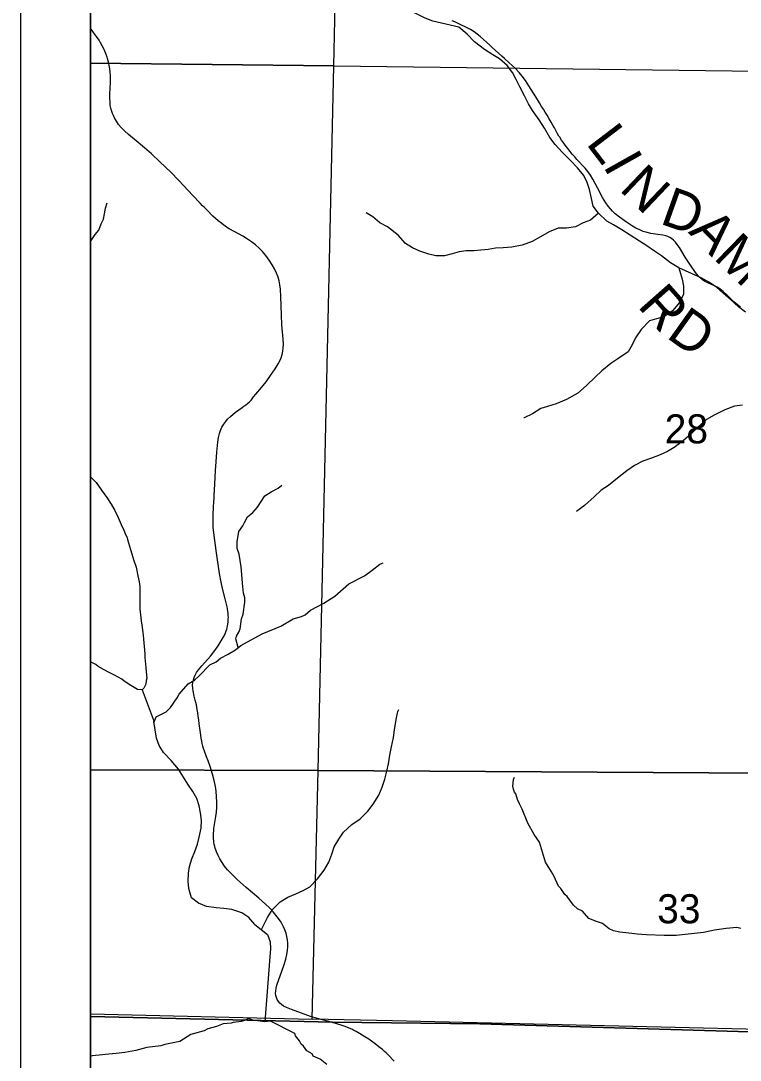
# Model space of a CAD drawing. Extents: x 0 to 34, y -8.9 to 22.
# Drawn here: x 23.617 to 24.652, y 15.928 to 17.424 of the extents above; entities that cross this region are included whole.
import ezdxf

# ---------------------------------------------------------------- set-up
doc = ezdxf.new("R2010")
doc.units = 0
for name, color, linetype in [('GM_X_Corporation', 7, 'Continuous'), ('GM_X_Minor_River', 7, 'Continuous'), ('GM_X_Section_Text', 7, 'Continuous'), ('GM_X_Township_Road', 7, 'Continuous'), ('GM_X_Township_Road_Text', 7, 'Continuous'), ('SH_Data', 7, 'Continuous')]:
    doc.layers.add(name, color=color, linetype=linetype)

msp = doc.modelspace()

# ---------------------------------------------------------------- linework, layer by layer
at = {"layer": 'GM_X_Corporation'}
msp.add_lwpolyline([(23.7167, 19.34), (23.7167, 14.6), (30.5167, 14.6)], dxfattribs=at)
for points in [[(23.7167, 19.34), (23.7167, 15.9913), (24.0651, 15.9828), (24.2771, 15.9807), (24.8268, 15.964), (25.6785, 15.9418), (25.7922, 15.939), (26.1186, 15.9366), (26.135, 17.3055), (26.1361, 17.3278), (26.1391, 17.8847), (26.1399, 18.3037), (25.7381, 18.312), (25.2083, 18.3108), (25.1045, 18.3117), (25.1124, 18.5932), (25.1216, 18.6194), (25.125, 18.6354), (25.1229, 18.6966), (25.1136, 18.8385), (25.1068, 18.8675), (25.1066, 19.3232), (25.0504, 19.3237), (24.5181, 19.3295)], [(23.7167, 18.338), (23.7167, 17.3635), (24.0671, 17.3595), (24.0882, 18.3313)], [(23.7167, 17.3635), (23.7167, 16.3462), (24.0445, 16.3452), (24.0671, 17.3595)], [(24.0671, 17.3595), (25.0983, 17.3466), (25.0882, 16.3389), (24.0445, 16.3452)], [(23.7167, 15.9913), (23.7167, 14.6), (28.1739, 14.6), (28.1809, 15.2987), (28.1918, 16.1509), (28.1846, 16.3341), (28.1817, 16.6637), (28.1928, 16.8054), (28.1882, 17.3108), (27.911, 17.3104), (27.4798, 17.3159), (27.0561, 17.3117), (26.7292, 17.3169), (26.394, 17.3229), (26.1361, 17.3278), (26.135, 17.3055), (26.1186, 15.9366), (25.7922, 15.939), (25.6785, 15.9418), (24.8268, 15.964), (24.2771, 15.9807), (24.0651, 15.9828)], [(23.7167, 16.3462), (23.7167, 15.9948), (24.0358, 15.9873), (24.0445, 16.3452)], [(24.0445, 16.3452), (25.0882, 16.3389), (25.0869, 15.9626), (24.1515, 15.9848), (24.0358, 15.9873)]]:
    msp.add_lwpolyline(points, close=True, dxfattribs=at)
at = {"layer": 'GM_X_Minor_River'}
for points in [[(24.2093, 17.4238), (24.1984, 17.428), (24.188, 17.4333), (24.1767, 17.4386), (24.167, 17.4439), (24.1569, 17.4461), (24.1447, 17.4466), (24.1333, 17.4447), (24.1214, 17.4428), (24.1107, 17.4417), (24.0993, 17.4394), (24.0897, 17.4386), (24.0787, 17.4394), (24.0679, 17.4436), (24.0577, 17.4478), (24.046, 17.4493), (24.0354, 17.4493), (24.0244, 17.4516), (24.0128, 17.455), (23.9838, 17.4816)], [(24.659, 17.0047), (24.649, 17.0127), (24.6372, 17.0238), (24.6276, 17.0317), (24.6173, 17.0408), (24.6065, 17.048), (24.5953, 17.0545), (24.5729, 17.0644), (24.5632, 17.0689), (24.5513, 17.0758), (24.5383, 17.0861), (24.5283, 17.0926), (24.5175, 17.1002), (24.5067, 17.107), (24.4934, 17.1158), (24.4815, 17.1235), (24.4692, 17.1308), (24.4595, 17.136), (24.4477, 17.1475), (24.4401, 17.1576), (24.4375, 17.1687), (24.4349, 17.1814), (24.4314, 17.1917), (24.4265, 17.2014), (24.4177, 17.2127), (24.4075, 17.223), (24.3957, 17.2352), (24.3855, 17.2462), (24.3778, 17.2563), (24.37, 17.2699), (24.3624, 17.2816), (24.353, 17.2952), (24.3472, 17.3049), (24.3412, 17.3161), (24.3348, 17.3293), (24.3291, 17.3397), (24.3241, 17.3498), (24.3165, 17.3599), (24.3054, 17.3695), (24.2958, 17.3755), (24.2838, 17.3828), (24.2694, 17.3939), (24.2588, 17.4053), (24.2466, 17.4152), (24.2093, 17.4238)], [(23.7167, 17.1072), (23.7177, 17.1081), (23.7236, 17.1166), (23.7288, 17.1228), (23.7321, 17.1319), (23.7354, 17.1388), (23.7371, 17.1464), (23.7385, 17.1548), (23.7407, 17.1625)], [(24.4477, 17.1475), (24.4364, 17.1372), (24.4256, 17.1334), (24.4148, 17.1277), (24.4018, 17.1259), (24.3896, 17.126), (24.3769, 17.1207), (24.3641, 17.1132), (24.3525, 17.1068), (24.3378, 17.1012), (24.3233, 17.0987), (24.3107, 17.0976), (24.2997, 17.0969), (24.289, 17.0953), (24.2787, 17.0942), (24.2684, 17.0934), (24.2574, 17.0934), (24.2474, 17.0919), (24.2371, 17.0888), (24.2263, 17.0862), (24.2138, 17.0858), (24.2036, 17.0885), (24.1909, 17.0927), (24.18, 17.0977), (24.1703, 17.1037), (24.1594, 17.1155), (24.1442, 17.1278), (24.133, 17.1335), (24.123, 17.1419), (24.1134, 17.1479)], [(24.5632, 17.0689), (24.5679, 17.0524), (24.5702, 17.0421), (24.5702, 17.0307), (24.5645, 17.0187), (24.5542, 17.0069), (24.5417, 16.9983), (24.531, 16.9952), (24.521, 16.9925), (24.5091, 16.98), (24.5011, 16.9678), (24.4962, 16.9577), (24.4902, 16.948), (24.4757, 16.9375), (24.4656, 16.931), (24.4527, 16.9205), (24.4429, 16.9113), (24.4303, 16.8992), (24.4182, 16.8883), (24.4015, 16.8794), (24.3868, 16.873), (24.3745, 16.8689), (24.3646, 16.8662), (24.3529, 16.8587), (24.3409, 16.853), (24.3402, 16.853)], [(24.655, 16.8711), (24.6432, 16.8697), (24.6297, 16.8644), (24.6143, 16.8566), (24.603, 16.8506), (24.5905, 16.8396), (24.581, 16.8297), (24.57, 16.8202), (24.5568, 16.81), (24.5471, 16.8043), (24.5366, 16.7997), (24.5239, 16.7949), (24.5116, 16.7904), (24.4993, 16.7843), (24.4887, 16.7767), (24.475, 16.7658), (24.4621, 16.7556), (24.4516, 16.7488), (24.4414, 16.7393), (24.4277, 16.7268), (24.416, 16.7181)], [(23.7167, 16.7677), (23.7249, 16.7595), (23.733, 16.7486), (23.7404, 16.7381), (23.7467, 16.7287), (23.7518, 16.7193), (23.7565, 16.7091), (23.7612, 16.6993), (23.7648, 16.6913), (23.7675, 16.6849), (23.7699, 16.6804), (23.7703, 16.6778), (23.7731, 16.6679), (23.7747, 16.6634), (23.7792, 16.6475), (23.7824, 16.6377), (23.7849, 16.6252), (23.7869, 16.6168), (23.7878, 16.61), (23.788, 16.5963), (23.7877, 16.5922), (23.788, 16.5777), (23.7889, 16.5694), (23.7898, 16.5607), (23.7907, 16.5542), (23.7911, 16.5508), (23.792, 16.5436), (23.7928, 16.5398), (23.7933, 16.5341), (23.7938, 16.5288), (23.7947, 16.5186), (23.7952, 16.5129), (23.7953, 16.5076), (23.7967, 16.4935), (23.7971, 16.4874), (23.7981, 16.478), (23.797, 16.4745), (23.7967, 16.4692), (23.7938, 16.4635), (23.7911, 16.4611), (23.7847, 16.4618), (23.7728, 16.4688), (23.7651, 16.474), (23.762, 16.4766), (23.7517, 16.4822), (23.7436, 16.4862), (23.7356, 16.4907), (23.7279, 16.4947), (23.7248, 16.4977), (23.7167, 16.5015)], [(23.9292, 16.522), (23.9262, 16.5347), (23.9268, 16.5385), (23.9305, 16.5443), (23.9324, 16.5492), (23.9344, 16.5633), (23.9365, 16.5702), (23.9389, 16.5873), (23.9388, 16.5938), (23.9372, 16.6006), (23.9358, 16.615), (23.9348, 16.6275), (23.9339, 16.6382), (23.9309, 16.6567), (23.9281, 16.6647), (23.9279, 16.6742), (23.9303, 16.6894), (23.9359, 16.6975), (23.9384, 16.7021), (23.9429, 16.7105), (23.9503, 16.7167), (23.9574, 16.7244), (23.9678, 16.7405), (23.9768, 16.7464), (23.9869, 16.7518), (23.9922, 16.7557)], [(23.7911, 16.4611), (23.8083, 16.4154), (23.8112, 16.4223), (23.8259, 16.4298), (23.8318, 16.4359), (23.8414, 16.4498), (23.8444, 16.4551), (23.8574, 16.4698), (23.8664, 16.4752), (23.8735, 16.4814), (23.8888, 16.4972), (23.8975, 16.5016), (23.9039, 16.507), (23.9148, 16.5125), (23.9257, 16.5187), (23.9332, 16.5249), (23.964, 16.5421), (23.9908, 16.5528), (24.0084, 16.5637), (24.0205, 16.567), (24.0258, 16.5693), (24.0333, 16.5759), (24.0528, 16.5861), (24.0686, 16.5962), (24.0888, 16.614), (24.111, 16.6254), (24.1222, 16.6335), (24.1331, 16.6424), (24.138, 16.644)], [(23.9628, 16.1163), (23.9715, 16.1335), (23.9787, 16.145), (23.9897, 16.156), (24.001, 16.1629), (24.0122, 16.1678), (24.023, 16.1723), (24.0327, 16.1777), (24.0437, 16.1891), (24.0533, 16.2017), (24.0597, 16.2132), (24.064, 16.2249), (24.0677, 16.2354), (24.0742, 16.2465), (24.081, 16.2562), (24.0928, 16.2672), (24.1049, 16.2758), (24.1159, 16.2865), (24.1235, 16.2965), (24.1315, 16.3095), (24.1365, 16.3211), (24.1403, 16.3327), (24.1434, 16.344), (24.1456, 16.3546), (24.1476, 16.367), (24.1499, 16.3791), (24.1527, 16.3927), (24.1542, 16.4037), (24.1566, 16.4184), (24.1593, 16.4301), (24.1605, 16.4331)], [(23.9532, 16.1235), (23.9449, 16.1337), (23.9348, 16.1401), (23.9202, 16.1452), (23.9088, 16.1464), (23.8978, 16.1475), (23.8839, 16.1495), (23.8722, 16.1541), (23.8623, 16.1621), (23.8582, 16.1751), (23.8574, 16.1854), (23.8578, 16.1972), (23.8593, 16.207), (23.8627, 16.2179), (23.8669, 16.2284), (23.8707, 16.2389), (23.8733, 16.2491), (23.876, 16.2623), (23.8764, 16.2733), (23.8753, 16.284), (23.8734, 16.2943), (23.8699, 16.3047), (23.8642, 16.3151), (23.857, 16.3253), (23.8505, 16.3354), (23.8433, 16.347), (23.8331, 16.3596), (23.8221, 16.3713), (23.8156, 16.3811), (23.8118, 16.3915), (23.8079, 16.4159)], [(24.6524, 16.1179), (24.6467, 16.119), (24.6315, 16.1176), (24.6148, 16.1151), (24.5986, 16.1118), (24.5595, 16.1077), (24.5421, 16.1075), (24.5166, 16.1086), (24.5033, 16.1095), (24.4957, 16.1105), (24.4786, 16.1125), (24.4694, 16.1143), (24.4633, 16.1172), (24.4537, 16.1247), (24.4449, 16.1276), (24.4338, 16.1323), (24.4245, 16.1425), (24.4176, 16.1461), (24.4119, 16.1514), (24.4025, 16.1638), (24.3991, 16.1668), (24.3936, 16.1754), (24.3901, 16.1788), (24.3842, 16.1927), (24.3799, 16.1995), (24.3717, 16.2131), (24.3628, 16.2422), (24.3551, 16.2531), (24.346, 16.2693), (24.3381, 16.2893), (24.3342, 16.2972), (24.3314, 16.3036), (24.3286, 16.3115), (24.3271, 16.3142), (24.3255, 16.3183), (24.3246, 16.3225), (24.3249, 16.3267), (24.3256, 16.3324), (24.3267, 16.3358)], [(23.9532, 16.1235), (23.9717, 16.1092), (23.9755, 16.0984), (23.976, 16.0885), (23.9748, 16.0768), (23.9676, 15.9836)], [(24.0108, 15.9665), (23.9759, 15.9845), (23.9676, 15.9836), (23.9504, 15.986), (23.9451, 15.9875), (23.9421, 15.9874), (23.9387, 15.9851), (23.9338, 15.9839), (23.922, 15.9826), (23.9194, 15.9817), (23.9076, 15.9804), (23.8982, 15.9765), (23.8858, 15.9732), (23.8805, 15.9705), (23.8612, 15.9653), (23.8454, 15.9551), (23.8239, 15.9506), (23.8182, 15.9486), (23.7981, 15.9464), (23.7823, 15.942), (23.7664, 15.9394), (23.7539, 15.9377), (23.738, 15.9363), (23.7342, 15.9359), (23.7194, 15.9345), (23.7167, 15.9337)], [(24.0567, 15.922), (24.0475, 15.9298), (24.0375, 15.9342), (24.0356, 15.9372), (24.0283, 15.9417), (24.0232, 15.9484), (24.0198, 15.9514), (24.0174, 15.9559), (24.012, 15.9631), (24.0108, 15.9665)]]:
    msp.add_lwpolyline(points, dxfattribs=at)
at = {"layer": 'GM_X_Township_Road'}
for points in [[(24.6521, 17.0119), (24.6472, 17.0157), (24.6425, 17.0198), (24.6323, 17.0297), (24.6269, 17.0348), (24.6225, 17.0383), (24.6183, 17.041), (24.6145, 17.043), (24.6048, 17.0472), (24.6009, 17.0491), (24.5972, 17.0515), (24.5939, 17.0542), (24.5909, 17.0574), (24.5874, 17.0618), (24.5801, 17.0725), (24.5726, 17.084), (24.5642, 17.0978), (24.5611, 17.1025), (24.5584, 17.1059), (24.5558, 17.1085), (24.5529, 17.1109), (24.5503, 17.1125), (24.5474, 17.1138), (24.5445, 17.1148), (24.5403, 17.1157), (24.5329, 17.1168), (24.523, 17.1182), (24.5176, 17.1194), (24.5122, 17.1211), (24.5071, 17.1232), (24.5015, 17.1259), (24.4969, 17.1287), (24.4879, 17.1345), (24.4779, 17.1418), (24.4719, 17.1466), (24.468, 17.1501), (24.4648, 17.1535), (24.4615, 17.1576), (24.4582, 17.1624), (24.4537, 17.17), (24.4462, 17.1838), (24.4429, 17.1901), (24.4394, 17.1964), (24.436, 17.2022), (24.4324, 17.2072), (24.4284, 17.212), (24.4246, 17.2161), (24.4204, 17.2206), (24.4167, 17.2247), (24.4135, 17.2283), (24.4101, 17.2323), (24.4069, 17.2363), (24.4035, 17.2405), (24.4018, 17.2427), (24.3997, 17.2455), (24.3968, 17.2494), (24.3947, 17.2524), (24.3919, 17.2566), (24.3909, 17.2584), (24.3885, 17.2627), (24.3863, 17.2666), (24.3844, 17.2702), (24.3821, 17.2742), (24.3797, 17.2784), (24.3769, 17.2831), (24.3737, 17.2884), (24.3711, 17.2927), (24.3686, 17.2969), (24.3659, 17.3011), (24.3627, 17.3064), (24.3576, 17.3148), (24.3477, 17.3308), (24.3426, 17.3383), (24.3379, 17.3447), (24.3336, 17.3498), (24.3277, 17.3559), (24.3194, 17.3639), (24.3127, 17.3699), (24.3087, 17.3734), (24.2949, 17.3858), (24.2913, 17.3891), (24.2776, 17.4017), (24.2732, 17.4053), (24.2687, 17.4085), (24.2634, 17.4118), (24.2568, 17.4152), (24.2497, 17.4186), (24.2449, 17.4207), (24.2411, 17.4226), (24.2373, 17.4244)], [(23.7485, 17.2911), (23.7476, 17.2936), (23.7462, 17.2984), (23.7453, 17.3022), (23.745, 17.3057), (23.7447, 17.3144), (23.7449, 17.3211), (23.7451, 17.3248), (23.7454, 17.3291), (23.7456, 17.3341), (23.7458, 17.3396), (23.7458, 17.3446), (23.7454, 17.3514), (23.7444, 17.3582), (23.743, 17.3648), (23.7414, 17.3702), (23.7408, 17.3719), (23.7394, 17.376), (23.7374, 17.3806), (23.7354, 17.3851), (23.7337, 17.3884), (23.7314, 17.3928), (23.7292, 17.3965), (23.7258, 17.4017), (23.7214, 17.4077), (23.7167, 17.4135), (23.7167, 17.4135)], [(23.8947, 16.7368), (23.8949, 16.7409), (23.8958, 16.7575), (23.8968, 16.7772), (23.8975, 16.7896), (23.8986, 16.8032), (23.9002, 16.818), (23.9013, 16.8247), (23.9026, 16.8301), (23.9041, 16.8348), (23.9061, 16.8393), (23.9086, 16.8436), (23.9114, 16.8476), (23.9142, 16.8508), (23.9182, 16.8546), (23.9257, 16.8608), (23.935, 16.8676), (23.9376, 16.8694), (23.9405, 16.8716), (23.943, 16.8736), (23.9458, 16.876), (23.9484, 16.8789), (23.9515, 16.8829), (23.9547, 16.8868), (23.9629, 16.8966), (23.9695, 16.9048), (23.9761, 16.9138), (23.9827, 16.9235), (23.9869, 16.9304), (23.9892, 16.9348), (23.9912, 16.9393), (23.9927, 16.944), (23.9937, 16.9489), (23.9942, 16.9538), (23.9944, 16.9588), (23.994, 16.9662), (23.9923, 16.9866), (23.9915, 17.0009), (23.9909, 17.0276), (23.9902, 17.0382), (23.9894, 17.0443), (23.9882, 17.0498), (23.9867, 17.0552), (23.9845, 17.061), (23.9816, 17.0672), (23.9782, 17.0731), (23.9739, 17.0799), (23.9691, 17.0864), (23.9643, 17.0921), (23.9596, 17.0971), (23.9545, 17.1016), (23.9486, 17.1062), (23.9429, 17.11), (23.936, 17.1141), (23.9245, 17.1203), (23.9164, 17.1249), (23.9112, 17.1283), (23.9057, 17.1323), (23.9004, 17.1366), (23.8931, 17.1432), (23.8842, 17.152), (23.8803, 17.156), (23.8781, 17.1581), (23.8746, 17.1616), (23.864, 17.173), (23.844, 17.1942), (23.8323, 17.2062), (23.8167, 17.2215), (23.8045, 17.2329), (23.7946, 17.2415), (23.7827, 17.2514), (23.7717, 17.2605), (23.7657, 17.2659), (23.761, 17.2708), (23.7574, 17.2751), (23.7542, 17.2796), (23.7514, 17.2845), (23.7498, 17.2878), (23.7485, 17.2911)], [(24.0661, 15.9821), (24.0653, 15.9823), (24.0435, 15.9882), (24.0334, 15.9912), (24.0205, 15.9957), (24.0059, 16.0011), (23.999, 16.0038), (23.9945, 16.0061), (23.9915, 16.0082), (23.9892, 16.0103), (23.9873, 16.0128), (23.9857, 16.0154), (23.9844, 16.0183), (23.9836, 16.0213), (23.9833, 16.0243), (23.9834, 16.0281), (23.9839, 16.0318), (23.985, 16.036), (23.9878, 16.0442), (23.9924, 16.0564), (23.9956, 16.0658), (23.9978, 16.0736), (23.9993, 16.0803), (24.0002, 16.0864), (24.0006, 16.0914), (24.0006, 16.0964), (24.0002, 16.1013), (23.9994, 16.1062), (23.9982, 16.1111), (23.9967, 16.1158), (23.9947, 16.1203), (23.9924, 16.1247), (23.9901, 16.1284), (23.9857, 16.1344), (23.9798, 16.1416), (23.9743, 16.1476), (23.9689, 16.1527), (23.959, 16.1612), (23.9411, 16.1766), (23.9281, 16.1882), (23.9201, 16.196), (23.9142, 16.2023), (23.9098, 16.2076), (23.9062, 16.2126), (23.903, 16.218), (23.9004, 16.2229), (23.8983, 16.2281), (23.8971, 16.2309), (23.8962, 16.2334), (23.8956, 16.2358), (23.895, 16.2386), (23.8946, 16.2413), (23.8942, 16.2443), (23.894, 16.2469), (23.8938, 16.2493), (23.8938, 16.2519), (23.8939, 16.2549), (23.8942, 16.2582), (23.8946, 16.2617), (23.8974, 16.2788), (23.8981, 16.285), (23.8985, 16.2925), (23.8987, 16.2999), (23.8984, 16.3074), (23.8976, 16.3154), (23.8966, 16.3222), (23.8948, 16.3307), (23.8925, 16.3397), (23.8889, 16.3509), (23.886, 16.3589), (23.8838, 16.365), (23.8809, 16.3732), (23.8796, 16.377), (23.8787, 16.3804), (23.8777, 16.3841), (23.877, 16.3875), (23.8763, 16.3919), (23.8755, 16.3961), (23.8746, 16.4029), (23.8734, 16.4121), (23.8726, 16.4181), (23.872, 16.4232), (23.8712, 16.4281), (23.8704, 16.4328), (23.8692, 16.4397), (23.8677, 16.4463), (23.8663, 16.4523), (23.8646, 16.4596), (23.8641, 16.4639), (23.8639, 16.4682), (23.8643, 16.4719), (23.8649, 16.4755), (23.866, 16.4791), (23.8675, 16.4825), (23.8696, 16.4862), (23.8724, 16.4903), (23.8773, 16.4959), (23.8895, 16.5099), (23.8956, 16.5177), (23.9005, 16.5247), (23.9065, 16.534), (23.9091, 16.5388), (23.9111, 16.5433), (23.9121, 16.546), (23.9129, 16.5485), (23.9135, 16.5506), (23.9141, 16.5533), (23.9145, 16.5556), (23.9149, 16.5582), (23.9151, 16.5606), (23.9152, 16.5631), (23.9153, 16.5657), (23.9152, 16.568), (23.915, 16.5716), (23.9147, 16.5742), (23.9141, 16.5779), (23.9135, 16.5808), (23.9109, 16.5923), (23.907, 16.6072), (23.905, 16.6163), (23.9027, 16.6285), (23.8979, 16.6616), (23.8947, 16.6836), (23.8936, 16.6953), (23.8932, 16.7033), (23.8933, 16.7119), (23.894, 16.7255), (23.8947, 16.7368)], [(24.1539, 15.9268), (24.1452, 15.9357), (24.1423, 15.9386), (24.1398, 15.9408), (24.1368, 15.9436), (24.1337, 15.9461), (24.1295, 15.9494), (24.1264, 15.9518), (24.1211, 15.9555), (24.1172, 15.9583), (24.1117, 15.962), (24.1079, 15.9644), (24.1038, 15.9668), (24.0993, 15.9694), (24.096, 15.9711), (24.0927, 15.9728), (24.0892, 15.9744), (24.0858, 15.9758), (24.0818, 15.9773), (24.0776, 15.9787), (24.0727, 15.9802), (24.0669, 15.9819), (24.0661, 15.9821)]]:
    msp.add_lwpolyline(points, dxfattribs=at)
at = {"layer": 'SH_Data'}
for points in [[(23.6167, 21.5), (30.6167, 21.5), (30.6167, 14.5), (23.6167, 14.5)], [(23.7167, 21.4), (30.5167, 21.4), (30.5167, 14.6), (23.7167, 14.6)]]:
    msp.add_lwpolyline(points, close=True, dxfattribs=at)

# ---------------------------------------------------------------- texts
at = {"layer": 'GM_X_Section_Text'}
for s, p in [('28', (24.543, 16.816)), ('33', (24.5322, 16.1252))]:
    msp.add_text(s, height=0.04186, rotation=0, dxfattribs=at).set_placement(p)
at = {"layer": 'GM_X_Township_Road_Text'}
for s, rotation, p in [('L', 307.3593, (24.4289, 17.2478)), ('I', 299.3169, (24.4536, 17.2158)), ('N', 316.4091, (24.4763, 17.1809)), ('D', 340.4044, (24.5345, 17.1329)), ('A', 314.1474, (24.5759, 17.1198)), ('M', 315.7458, (24.6119, 17.0827)), ('R', 311.4485, (24.5026, 17.0135)), ('D', 324.5887, (24.5438, 16.9692))]:
    msp.add_text(s, height=0.0568, rotation=rotation, dxfattribs=at).set_placement(p)

doc.saveas('drawing.dxf')
